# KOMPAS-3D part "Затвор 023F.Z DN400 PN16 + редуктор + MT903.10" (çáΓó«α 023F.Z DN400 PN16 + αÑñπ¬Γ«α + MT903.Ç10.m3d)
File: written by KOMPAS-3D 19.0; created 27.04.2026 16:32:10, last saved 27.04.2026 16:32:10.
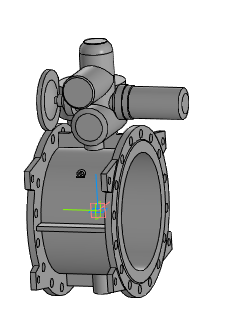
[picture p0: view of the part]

Document properties: Полное имя файла: ..\Затвор 023F.Z DN400 PN16 + редуктор + MT903.А10.a3d

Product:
- Part/product: Затвор 023F.Z DN400 PN16 + редуктор + MT903.10
    Масса: 275.441

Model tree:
1. Операция без истории:1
